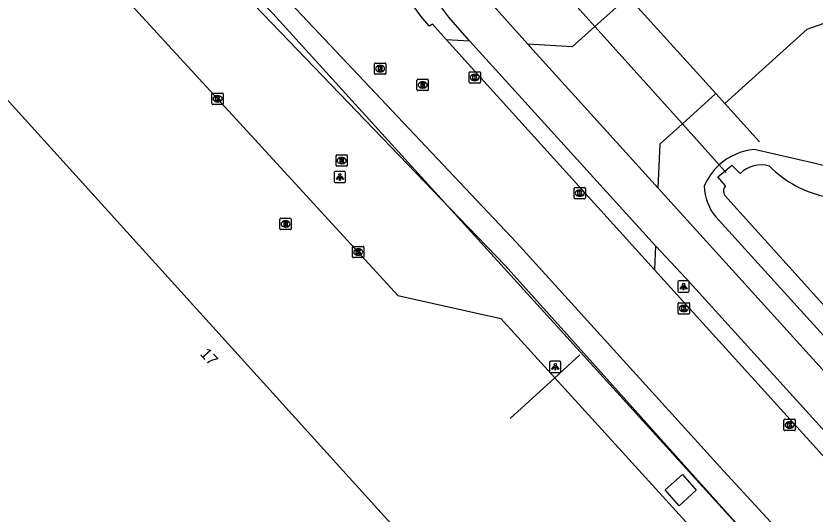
# Model space of a CAD drawing. Extents: x 156141 to 158132, y 385651 to 388399.
# Drawn here: x 156616.3 to 156687.2, y 387557.5 to 387601.7 of the extents above; entities that cross this region are included whole.
import ezdxf

# ---------------------------------------------------------------- set-up
doc = ezdxf.new("R2010")
doc.units = 0
for name, color, linetype in [('IMGEO_Berm_groen', 7, 'Continuous'), ('IMGEO_Duiker', 7, 'Continuous'), ('IMGEO_Fietspad_gesloten', 7, 'Continuous'), ('IMGEO_Groenvoorziening', 7, 'Continuous'), ('IMGEO_Hek', 7, 'Continuous'), ('IMGEO_Kolk', 7, 'Continuous'), ('IMGEO_Lichtpunt', 7, 'Continuous'), ('IMGEO_Pand', 7, 'Continuous'), ('IMGEO_Pand_nummerreeks', 7, 'Continuous'), ('IMGEO_Rijbaan_lokaal_gesloten', 7, 'Continuous'), ('IMGEO_Rijbaan_lokaal_open', 7, 'Continuous'), ('IMGEO_Rioolput', 7, 'Continuous'), ('IMGEO_Waterloop', 7, 'Continuous')]:
    doc.layers.add(name, color=color, linetype=linetype)

msp = doc.modelspace()

# ---------------------------------------------------------------- linework, layer by layer
at = {"layer": 'IMGEO_Berm_groen'}
msp.add_lwpolyline([(156619.894, 387618.693), (156621.328, 387618.297), (156622.076, 387617.962), (156623.109, 387617.268), (156623.862, 387616.763), (156654.792, 387584.595), (156659.669, 387579.524), (156664.874, 387573.724), (156670.466, 387567.492), (156676.557, 387560.705), (156683.035, 387553.487)], dxfattribs=at)
at = {"layer": 'IMGEO_Duiker'}
msp.add_lwpolyline([(156665.589, 387602.994), (156665.75, 387602.815), (156667.62, 387600.734), (156675.388, 387592.091), (156678.654, 387588.457), (156679.148, 387587.907), (156679.267, 387587.775)], dxfattribs=at)
at = {"layer": 'IMGEO_Fietspad_gesloten'}
for points in [[(156636.612, 387631.386), (156653.428, 387608.928), (156657.588, 387603.771), (156661.694, 387599.163)], [(156656.514, 387599.474), (156654.677, 387601.565), (156653.249, 387603.495), (156633.874, 387629.22)], [(156781.004, 387467.422), (156751.5, 387500), (156673.243, 387586.408)], [(156710.195, 387540.331), (156675.728, 387578.392), (156673.017, 387581.269)]]:
    msp.add_lwpolyline(points, dxfattribs=at)
at = {"layer": 'IMGEO_Groenvoorziening'}
for points in [[(156678.365, 387594.783), (156679.166, 387593.896), (156686.466, 387600.496), (156688.888, 387601.354), (156691.163, 387600.15), (156724.535, 387562.997), (156709.488, 387563.912), (156707.811, 387562.233), (156752.805, 387512.437), (156782.941, 387479.122), (156787.929, 387473.603)], [(156687.155, 387588.587), (156681.743, 387589.828)], [(156678.358, 387583.842), (156778.225, 387473.7)], [(156675.387, 387560.984), (156676.621, 387559.59), (156675.111, 387558.213), (156673.862, 387559.615), (156675.387, 387560.984)]]:
    msp.add_lwpolyline(points, dxfattribs=at)
for centre, radius, start, end in [((156682.266, 387584.485), 5.368, 95.58688, 132.27957), ((156682.592, 387584.256), 5.758, 133.14814, 156.16499), ((156675.018, 387537.83), 52.188, 67.60215, 76.55146), ((156681.767, 387586.692), 4.443, 181.40417, 219.89565)]:
    msp.add_arc(centre, radius, start, end, dxfattribs=at)
at = {"layer": 'IMGEO_Hek'}
for points in [[(156621.815, 387617.999), (156623.877, 387616.835), (156639.077, 387601.905), (156683.035, 387553.487)], [(156670.587, 387603.403), (156678.365, 387594.783), (156679.166, 387593.896), (156682.233, 387590.498)], [(156679.166, 387593.896), (156686.466, 387600.496), (156688.888, 387601.354), (156691.163, 387600.15), (156724.535, 387562.997), (156709.488, 387563.912), (156707.811, 387562.233)], [(156660.126, 387565.971), (156664.072, 387569.578), (156666.283, 387571.6)]]:
    msp.add_lwpolyline(points, dxfattribs=at)
at = {"layer": 'IMGEO_Kolk'}
for p, q in [((156656.472, 387595.791), (156656.472, 387596.643)), ((156656.547, 387596.717), (156657.399, 387596.717)), ((156656.96, 387596.497), (156656.985, 387596.497)), ((156657.473, 387596.643), (156657.473, 387595.791)), ((156657.399, 387595.717), (156656.547, 387595.717)), ((156656.983, 387595.937), (156656.958, 387595.937)), ((156633.744, 387594.83), (156634.596, 387594.83)), ((156633.669, 387593.904), (156633.669, 387594.756)), ((156634.157, 387594.61), (156634.182, 387594.61)), ((156634.67, 387594.756), (156634.67, 387593.904)), ((156634.596, 387593.83), (156633.744, 387593.83)), ((156634.18, 387594.05), (156634.155, 387594.05)), ((156665.787, 387585.525), (156665.787, 387586.377)), ((156665.862, 387586.451), (156666.714, 387586.451)), ((156666.788, 387586.377), (156666.788, 387585.525)), ((156666.298, 387585.671), (156666.273, 387585.671)), ((156666.275, 387586.231), (156666.3, 387586.231)), ((156666.714, 387585.451), (156665.862, 387585.451)), ((156646.143, 387580.303), (156646.143, 387581.155)), ((156646.218, 387581.229), (156647.07, 387581.229)), ((156646.631, 387581.009), (156646.656, 387581.009)), ((156647.144, 387581.155), (156647.144, 387580.303)), ((156647.07, 387580.229), (156646.218, 387580.229)), ((156646.654, 387580.449), (156646.629, 387580.449)), ((156675.024, 387575.302), (156675.024, 387576.154)), ((156675.099, 387576.228), (156675.951, 387576.228)), ((156675.512, 387576.008), (156675.537, 387576.008)), ((156676.025, 387576.154), (156676.025, 387575.302)), ((156675.951, 387575.228), (156675.099, 387575.228)), ((156675.535, 387575.448), (156675.51, 387575.448)), ((156684.401, 387564.958), (156684.401, 387565.81)), ((156684.476, 387565.884), (156685.328, 387565.884)), ((156685.402, 387565.81), (156685.402, 387564.958)), ((156684.912, 387565.104), (156684.887, 387565.104)), ((156684.889, 387565.664), (156684.914, 387565.664)), ((156685.328, 387564.884), (156684.476, 387564.884))]:
    msp.add_line(p, q, dxfattribs=at)
for points in [[(156656.472, 387595.791), (156656.472, 387596.643)], [(156656.547, 387596.717), (156657.399, 387596.717)], [(156656.793, 387596.417), (156656.916, 387596.417), (156656.916, 387596.266), (156657.046, 387596.417), (156657.21, 387596.417), (156657.064, 387596.266), (156657.217, 387596.017), (156657.065, 387596.017), (156656.98, 387596.181), (156656.916, 387596.114), (156656.916, 387596.017), (156656.793, 387596.017), (156656.793, 387596.417)], [(156657.473, 387596.643), (156657.473, 387595.791)], [(156657.399, 387595.717), (156656.547, 387595.717)], [(156633.744, 387594.83), (156634.596, 387594.83)], [(156633.669, 387593.904), (156633.669, 387594.756)], [(156633.99, 387594.53), (156634.113, 387594.53), (156634.113, 387594.379), (156634.243, 387594.53), (156634.407, 387594.53), (156634.261, 387594.379), (156634.414, 387594.13), (156634.262, 387594.13), (156634.177, 387594.294), (156634.113, 387594.227), (156634.113, 387594.13), (156633.99, 387594.13), (156633.99, 387594.53)], [(156634.67, 387594.756), (156634.67, 387593.904)], [(156634.596, 387593.83), (156633.744, 387593.83)], [(156665.787, 387585.525), (156665.787, 387586.377)], [(156665.862, 387586.451), (156666.714, 387586.451)], [(156666.788, 387586.377), (156666.788, 387585.525)], [(156666.108, 387586.151), (156666.231, 387586.151), (156666.231, 387586), (156666.361, 387586.151), (156666.525, 387586.151), (156666.379, 387586), (156666.532, 387585.751), (156666.38, 387585.751), (156666.295, 387585.915), (156666.231, 387585.848), (156666.231, 387585.751), (156666.108, 387585.751), (156666.108, 387586.151)], [(156666.714, 387585.451), (156665.862, 387585.451)], [(156646.143, 387580.303), (156646.143, 387581.155)], [(156646.218, 387581.229), (156647.07, 387581.229)], [(156646.464, 387580.929), (156646.587, 387580.929), (156646.587, 387580.778), (156646.717, 387580.929), (156646.881, 387580.929), (156646.735, 387580.778), (156646.888, 387580.529), (156646.736, 387580.529), (156646.651, 387580.693), (156646.587, 387580.626), (156646.587, 387580.529), (156646.464, 387580.529), (156646.464, 387580.929)], [(156647.144, 387581.155), (156647.144, 387580.303)], [(156647.07, 387580.229), (156646.218, 387580.229)], [(156675.024, 387575.302), (156675.024, 387576.154)], [(156675.099, 387576.228), (156675.951, 387576.228)], [(156675.345, 387575.928), (156675.468, 387575.928), (156675.468, 387575.777), (156675.598, 387575.928), (156675.762, 387575.928), (156675.616, 387575.777), (156675.769, 387575.528), (156675.617, 387575.528), (156675.532, 387575.692), (156675.468, 387575.625), (156675.468, 387575.528), (156675.345, 387575.528), (156675.345, 387575.928)], [(156676.025, 387576.154), (156676.025, 387575.302)], [(156675.951, 387575.228), (156675.099, 387575.228)], [(156684.401, 387564.958), (156684.401, 387565.81)], [(156684.476, 387565.884), (156685.328, 387565.884)], [(156685.402, 387565.81), (156685.402, 387564.958)], [(156684.722, 387565.584), (156684.845, 387565.584), (156684.845, 387565.433), (156684.975, 387565.584), (156685.139, 387565.584), (156684.993, 387565.433), (156685.146, 387565.184), (156684.994, 387565.184), (156684.909, 387565.348), (156684.845, 387565.281), (156684.845, 387565.184), (156684.722, 387565.184), (156684.722, 387565.584)], [(156685.328, 387564.884), (156684.476, 387564.884)]]:
    msp.add_lwpolyline(points, dxfattribs=at)
for centre, start, end in [((156656.549, 387596.641), 91.55205, 178.44795), ((156656.549, 387596.641), 91.55205, 178.44795), ((156657.397, 387596.641), 1.55205, 88.44795), ((156657.397, 387596.641), 1.55205, 88.44795), ((156656.549, 387595.793), 181.55205, 268.44795), ((156656.549, 387595.793), 181.55205, 268.44795), ((156657.397, 387595.793), 271.55205, 358.44795), ((156657.397, 387595.793), 271.55205, 358.44795), ((156633.746, 387594.754), 91.55205, 178.44795), ((156633.746, 387594.754), 91.55205, 178.44795), ((156634.594, 387594.754), 1.55205, 88.44795), ((156634.594, 387594.754), 1.55205, 88.44795), ((156633.746, 387593.906), 181.55205, 268.44795), ((156633.746, 387593.906), 181.55205, 268.44795), ((156634.594, 387593.906), 271.55205, 358.44795), ((156634.594, 387593.906), 271.55205, 358.44795), ((156665.864, 387586.375), 91.55205, 178.44795), ((156665.864, 387586.375), 91.55205, 178.44795), ((156666.712, 387586.375), 1.55205, 88.44795), ((156666.712, 387586.375), 1.55205, 88.44795), ((156665.864, 387585.527), 181.55205, 268.44795), ((156665.864, 387585.527), 181.55205, 268.44795), ((156666.712, 387585.527), 271.55205, 358.44795), ((156666.712, 387585.527), 271.55205, 358.44795), ((156646.22, 387581.153), 91.55205, 178.44795), ((156646.22, 387581.153), 91.55205, 178.44795), ((156647.068, 387581.153), 1.55205, 88.44795), ((156647.068, 387581.153), 1.55205, 88.44795), ((156646.22, 387580.305), 181.55205, 268.44795), ((156646.22, 387580.305), 181.55205, 268.44795), ((156647.068, 387580.305), 271.55205, 358.44795), ((156647.068, 387580.305), 271.55205, 358.44795), ((156675.101, 387576.152), 91.55205, 178.44795), ((156675.101, 387576.152), 91.55205, 178.44795), ((156675.949, 387576.152), 1.55205, 88.44795), ((156675.949, 387576.152), 1.55205, 88.44795), ((156675.101, 387575.304), 181.55205, 268.44795), ((156675.101, 387575.304), 181.55205, 268.44795), ((156675.949, 387575.304), 271.55205, 358.44795), ((156675.949, 387575.304), 271.55205, 358.44795), ((156684.478, 387565.808), 91.55205, 178.44795), ((156684.478, 387565.808), 91.55205, 178.44795), ((156685.326, 387565.808), 1.55205, 88.44795), ((156685.326, 387565.808), 1.55205, 88.44795), ((156684.478, 387564.96), 181.55205, 268.44795), ((156684.478, 387564.96), 181.55205, 268.44795), ((156685.326, 387564.96), 271.55205, 358.44795), ((156685.326, 387564.96), 271.55205, 358.44795)]:
    msp.add_arc(centre, 0.0765, start, end, dxfattribs=at)
for centre, major_axis, ratio, start_param, end_param in [((156656.959, 387596.217), (-0.387, 0.002), 0.722429, 4.712389, 7.853982), ((156656.984, 387596.217), (-0.39, 0.002), 0.717154, 1.570796, 4.712389), ((156634.156, 387594.33), (-0.387, 0.002), 0.722429, 4.712389, 7.853982), ((156634.181, 387594.33), (-0.39, 0.002), 0.717154, 1.570796, 4.712389), ((156666.274, 387585.951), (-0.387, 0.002), 0.722429, 4.712389, 7.853982), ((156666.299, 387585.951), (-0.39, 0.002), 0.717154, 1.570796, 4.712389), ((156646.63, 387580.729), (-0.387, 0.002), 0.722429, 4.712389, 7.853982), ((156646.655, 387580.729), (-0.39, 0.002), 0.717154, 1.570796, 4.712389), ((156675.511, 387575.728), (-0.387, 0.002), 0.722429, 4.712389, 7.853982), ((156675.536, 387575.728), (-0.39, 0.002), 0.717154, 1.570796, 4.712389), ((156684.888, 387565.384), (-0.387, 0.002), 0.722429, 4.712389, 7.853982), ((156684.913, 387565.384), (-0.39, 0.002), 0.717154, 1.570796, 4.712389)]:
    msp.add_ellipse(centre, major_axis=major_axis, ratio=ratio, start_param=start_param, end_param=end_param, dxfattribs=at)
at = {"layer": 'IMGEO_Lichtpunt'}
for p, q in [((156644.511, 387587.787), (156644.511, 387586.98)), ((156644.511, 387587.787), (156644.511, 387586.98)), ((156645.413, 387587.882), (156644.605, 387587.882)), ((156645.413, 387587.882), (156644.605, 387587.882)), ((156645.507, 387586.98), (156645.507, 387587.787)), ((156645.507, 387586.98), (156645.507, 387587.787)), ((156644.605, 387586.886), (156645.413, 387586.886)), ((156644.605, 387586.886), (156645.413, 387586.886)), ((156674.996, 387578.071), (156674.996, 387577.264)), ((156674.996, 387578.071), (156674.996, 387577.264)), ((156675.898, 387578.166), (156675.09, 387578.166)), ((156675.898, 387578.166), (156675.09, 387578.166)), ((156675.992, 387577.264), (156675.992, 387578.071)), ((156675.992, 387577.264), (156675.992, 387578.071)), ((156675.09, 387577.17), (156675.898, 387577.17)), ((156675.09, 387577.17), (156675.898, 387577.17)), ((156663.619, 387570.94), (156663.619, 387570.133)), ((156663.619, 387570.94), (156663.619, 387570.133)), ((156664.521, 387571.035), (156663.713, 387571.035)), ((156664.521, 387571.035), (156663.713, 387571.035)), ((156664.615, 387570.133), (156664.615, 387570.94)), ((156664.615, 387570.133), (156664.615, 387570.94)), ((156663.713, 387570.039), (156664.521, 387570.039)), ((156663.713, 387570.039), (156664.521, 387570.039))]:
    msp.add_line(p, q, dxfattribs=at)
for points in [[(156644.885, 387587.451), (156644.924, 387587.423), (156644.736, 387587.161), (156644.698, 387587.188), (156644.885, 387587.451)], [(156644.987, 387587.403), (156645.034, 387587.403), (156645.034, 387587.081), (156644.987, 387587.081), (156644.987, 387587.403)], [(156645.097, 387587.423), (156645.135, 387587.45), (156645.322, 387587.188), (156645.283, 387587.16), (156645.097, 387587.423)], [(156675.37, 387577.735), (156675.409, 387577.707), (156675.221, 387577.445), (156675.183, 387577.472), (156675.37, 387577.735)], [(156675.472, 387577.687), (156675.519, 387577.687), (156675.519, 387577.365), (156675.472, 387577.365), (156675.472, 387577.687)], [(156675.582, 387577.707), (156675.62, 387577.734), (156675.807, 387577.472), (156675.768, 387577.444), (156675.582, 387577.707)], [(156663.993, 387570.604), (156664.032, 387570.576), (156663.844, 387570.314), (156663.806, 387570.341), (156663.993, 387570.604)], [(156664.095, 387570.556), (156664.142, 387570.556), (156664.142, 387570.234), (156664.095, 387570.234), (156664.095, 387570.556)], [(156664.205, 387570.576), (156664.243, 387570.603), (156664.43, 387570.341), (156664.391, 387570.313), (156664.205, 387570.576)]]:
    msp.add_lwpolyline(points, dxfattribs=at)
for centre in [(156645.01, 387587.585), (156675.495, 387577.869), (156664.118, 387570.738)]:
    msp.add_circle(centre, 0.0994, dxfattribs=at)
for centre, start, end in [((156644.605, 387587.787), 90, 180), ((156644.605, 387587.787), 90, 180), ((156645.413, 387587.787), 0, 90), ((156645.413, 387587.787), 0, 90), ((156644.605, 387586.98), 180, 270), ((156644.605, 387586.98), 180, 270), ((156645.413, 387586.98), 270, 0), ((156645.413, 387586.98), 270, 360), ((156675.09, 387578.071), 90, 180), ((156675.09, 387578.071), 90, 180), ((156675.898, 387578.071), 0, 90), ((156675.898, 387578.071), 0, 90), ((156675.09, 387577.264), 180, 270), ((156675.09, 387577.264), 180, 270), ((156675.898, 387577.264), 270, 0), ((156675.898, 387577.264), 270, 360), ((156663.713, 387570.94), 90, 180), ((156663.713, 387570.94), 90, 180), ((156664.521, 387570.94), 0, 90), ((156664.521, 387570.94), 0, 90), ((156663.713, 387570.133), 180, 270), ((156663.713, 387570.133), 180, 270), ((156664.521, 387570.133), 270, 0), ((156664.521, 387570.133), 270, 360)]:
    msp.add_arc(centre, 0.0946, start, end, dxfattribs=at)
at = {"layer": 'IMGEO_Pand'}
msp.add_lwpolyline([(156649.493, 387556.673), (156611.15, 387599.011), (156601.503, 387590.29)], dxfattribs=at)
at = {"layer": 'IMGEO_Rijbaan_lokaal_gesloten'}
for points in [[(156654.437, 387599.58), (156653.22, 387600.956), (156652.968, 387600.758), (156652.324, 387601.511), (156643.266, 387613.813), (156635.328, 387624.409), (156631.221, 387629.55)], [(156622.677, 387622.734), (156627.604, 387616.653), (156660.668, 387581.568), (156679.046, 387561.32), (156683.223, 387556.751)], [(156620.65, 387609.049), (156621.494, 387608.144), (156634.17, 387594.33), (156646.644, 387580.729), (156650.158, 387576.878), (156659.292, 387574.843), (156664.072, 387569.578), (156678.969, 387553.169)], [(156672.91, 387579.145), (156654.437, 387599.58)], [(156709.034, 387539.277), (156672.91, 387579.145)]]:
    msp.add_lwpolyline(points, dxfattribs=at)
at = {"layer": 'IMGEO_Rijbaan_lokaal_open'}
for points in [[(156670.587, 387603.403), (156667.62, 387600.734), (156665.621, 387598.937), (156661.694, 387599.163)], [(156678.365, 387594.783), (156670.587, 387603.403)], [(156654.437, 387599.58), (156656.514, 387599.474)], [(156673.017, 387581.269), (156656.514, 387599.474)], [(156661.694, 387599.163), (156661.859, 387598.978), (156673.243, 387586.408)], [(156673.243, 387586.408), (156673.43, 387590.319), (156675.388, 387592.091), (156678.365, 387594.783)], [(156673.017, 387581.269), (156672.91, 387579.145)]]:
    msp.add_lwpolyline(points, dxfattribs=at)
at = {"layer": 'IMGEO_Rioolput'}
for p, q in [((156648.082, 387596.574), (156648.082, 387597.426)), ((156648.157, 387597.5), (156649.009, 387597.5)), ((156648.57, 387597.28), (156648.595, 387597.28)), ((156649.083, 387597.426), (156649.083, 387596.574)), ((156649.009, 387596.5), (156648.157, 387596.5)), ((156648.593, 387596.72), (156648.568, 387596.72)), ((156651.852, 387595.127), (156651.852, 387595.979)), ((156651.927, 387596.053), (156652.779, 387596.053)), ((156652.34, 387595.833), (156652.365, 387595.833)), ((156652.853, 387595.979), (156652.853, 387595.127)), ((156652.779, 387595.053), (156651.927, 387595.053)), ((156652.363, 387595.273), (156652.338, 387595.273)), ((156644.672, 387588.414), (156644.672, 387589.266)), ((156644.747, 387589.34), (156645.599, 387589.34)), ((156645.16, 387589.12), (156645.185, 387589.12)), ((156645.673, 387589.266), (156645.673, 387588.414)), ((156645.183, 387588.56), (156645.158, 387588.56)), ((156645.599, 387588.34), (156644.747, 387588.34)), ((156639.697, 387582.794), (156639.697, 387583.646)), ((156639.772, 387583.72), (156640.624, 387583.72)), ((156640.185, 387583.5), (156640.21, 387583.5)), ((156640.698, 387583.646), (156640.698, 387582.794)), ((156640.624, 387582.72), (156639.772, 387582.72)), ((156640.208, 387582.94), (156640.183, 387582.94))]:
    msp.add_line(p, q, dxfattribs=at)
for points in [[(156648.082, 387596.574), (156648.082, 387597.426)], [(156648.157, 387597.5), (156649.009, 387597.5)], [(156648.671, 387597.198), (156648.419, 387597.2), (156648.419, 387596.8)], [(156648.419, 387596.8), (156648.543, 387596.8), (156648.543, 387596.962), (156648.554, 387596.962)], [(156648.597, 387597.119), (156648.543, 387597.119), (156648.543, 387597.038)], [(156648.543, 387597.038), (156648.595, 387597.038)], [(156648.601, 387596.933), (156648.672, 387596.8), (156648.812, 387596.8), (156648.747, 387596.926)], [(156649.083, 387597.426), (156649.083, 387596.574)], [(156649.009, 387596.5), (156648.157, 387596.5)], [(156651.852, 387595.127), (156651.852, 387595.979)], [(156651.927, 387596.053), (156652.779, 387596.053)], [(156652.441, 387595.751), (156652.189, 387595.753), (156652.189, 387595.353)], [(156652.189, 387595.353), (156652.313, 387595.353), (156652.313, 387595.515), (156652.324, 387595.515)], [(156652.367, 387595.672), (156652.313, 387595.672), (156652.313, 387595.591)], [(156652.313, 387595.591), (156652.365, 387595.591)], [(156652.371, 387595.486), (156652.442, 387595.353), (156652.582, 387595.353), (156652.517, 387595.479)], [(156652.853, 387595.979), (156652.853, 387595.127)], [(156652.779, 387595.053), (156651.927, 387595.053)], [(156644.672, 387588.414), (156644.672, 387589.266)], [(156644.747, 387589.34), (156645.599, 387589.34)], [(156645.673, 387589.266), (156645.673, 387588.414)], [(156645.261, 387589.038), (156645.009, 387589.04), (156645.009, 387588.64)], [(156645.009, 387588.64), (156645.133, 387588.64), (156645.133, 387588.802), (156645.144, 387588.802)], [(156645.187, 387588.959), (156645.133, 387588.959), (156645.133, 387588.878)], [(156645.133, 387588.878), (156645.185, 387588.878)], [(156645.191, 387588.773), (156645.262, 387588.64), (156645.402, 387588.64), (156645.337, 387588.766)], [(156645.599, 387588.34), (156644.747, 387588.34)], [(156639.697, 387582.794), (156639.697, 387583.646)], [(156639.772, 387583.72), (156640.624, 387583.72)], [(156640.698, 387583.646), (156640.698, 387582.794)], [(156640.624, 387582.72), (156639.772, 387582.72)], [(156640.286, 387583.418), (156640.034, 387583.42), (156640.034, 387583.02)], [(156640.034, 387583.02), (156640.158, 387583.02), (156640.158, 387583.182), (156640.169, 387583.182)], [(156640.212, 387583.339), (156640.158, 387583.339), (156640.158, 387583.258)], [(156640.158, 387583.258), (156640.21, 387583.258)], [(156640.216, 387583.153), (156640.287, 387583.02), (156640.427, 387583.02), (156640.362, 387583.146)]]:
    msp.add_lwpolyline(points, dxfattribs=at)
for centre, radius, start, end in [((156648.159, 387597.424), 0.0765, 91.55205, 178.44795), ((156648.159, 387597.424), 0.0765, 91.55205, 178.44795), ((156648.553, 387596.909), 0.0533, 26.02933, 88.69889), ((156648.579, 387597.227), 0.19, 274.7715, 282.96867), ((156648.603, 387597.023), 0.0964, 77.00612, 93.18647), ((156648.617, 387597.08), 0.0378, 276.66336, 79.67722), ((156648.67, 387597.088), 0.109, 350.36119, 89.41601), ((156648.668, 387597.088), 0.112, 277.58423, 350.98172), ((156648.652, 387596.873), 0.108, 29.51342, 73.79051), ((156649.007, 387597.424), 0.0765, 1.55205, 88.44795), ((156649.007, 387597.424), 0.0765, 1.55205, 88.44795), ((156648.159, 387596.576), 0.0765, 181.55205, 268.44795), ((156648.159, 387596.576), 0.0765, 181.55205, 268.44795), ((156649.007, 387596.576), 0.0765, 271.55205, 358.44795), ((156649.007, 387596.576), 0.0765, 271.55205, 358.44795), ((156651.929, 387595.977), 0.0765, 91.55205, 178.44795), ((156651.929, 387595.977), 0.0765, 91.55205, 178.44795), ((156652.323, 387595.462), 0.0533, 26.02933, 88.69889), ((156652.349, 387595.78), 0.19, 274.7715, 282.96867), ((156652.373, 387595.576), 0.0964, 77.00612, 93.18647), ((156652.387, 387595.633), 0.0378, 276.66336, 79.67722), ((156652.44, 387595.641), 0.109, 350.36119, 89.41601), ((156652.438, 387595.641), 0.112, 277.58423, 350.98172), ((156652.422, 387595.426), 0.108, 29.51342, 73.79051), ((156652.777, 387595.977), 0.0765, 1.55205, 88.44795), ((156652.777, 387595.977), 0.0765, 1.55205, 88.44795), ((156651.929, 387595.129), 0.0765, 181.55205, 268.44795), ((156651.929, 387595.129), 0.0765, 181.55205, 268.44795), ((156652.777, 387595.129), 0.0765, 271.55205, 358.44795), ((156652.777, 387595.129), 0.0765, 271.55205, 358.44795), ((156644.749, 387589.264), 0.0765, 91.55205, 178.44795), ((156644.749, 387589.264), 0.0765, 91.55205, 178.44795), ((156645.597, 387589.264), 0.0765, 1.55205, 88.44795), ((156645.597, 387589.264), 0.0765, 1.55205, 88.44795), ((156644.749, 387588.416), 0.0765, 181.55205, 268.44795), ((156644.749, 387588.416), 0.0765, 181.55205, 268.44795), ((156645.143, 387588.749), 0.0533, 26.02933, 88.69889), ((156645.169, 387589.067), 0.19, 274.7715, 282.96867), ((156645.193, 387588.863), 0.0964, 77.00612, 93.18647), ((156645.207, 387588.92), 0.0378, 276.66336, 79.67722), ((156645.26, 387588.928), 0.109, 350.36119, 89.41601), ((156645.258, 387588.928), 0.112, 277.58423, 350.98172), ((156645.242, 387588.713), 0.108, 29.51342, 73.79051), ((156645.597, 387588.416), 0.0765, 271.55205, 358.44795), ((156645.597, 387588.416), 0.0765, 271.55205, 358.44795), ((156639.774, 387583.644), 0.0765, 91.55205, 178.44795), ((156639.774, 387583.644), 0.0765, 91.55205, 178.44795), ((156640.622, 387583.644), 0.0765, 1.55205, 88.44795), ((156640.622, 387583.644), 0.0765, 1.55205, 88.44795), ((156639.774, 387582.796), 0.0765, 181.55205, 268.44795), ((156639.774, 387582.796), 0.0765, 181.55205, 268.44795), ((156640.168, 387583.129), 0.0533, 26.02933, 88.69889), ((156640.194, 387583.447), 0.19, 274.7715, 282.96867), ((156640.218, 387583.243), 0.0964, 77.00612, 93.18647), ((156640.232, 387583.3), 0.0378, 276.66336, 79.67722), ((156640.285, 387583.308), 0.109, 350.36119, 89.41601), ((156640.283, 387583.308), 0.112, 277.58423, 350.98172), ((156640.267, 387583.093), 0.108, 29.51342, 73.79051), ((156640.622, 387582.796), 0.0765, 271.55205, 358.44795), ((156640.622, 387582.796), 0.0765, 271.55205, 358.44795)]:
    msp.add_arc(centre, radius, start, end, dxfattribs=at)
for centre, major_axis, ratio, start_param, end_param in [((156648.569, 387597), (-0.387, 0.002), 0.722429, 4.712389, 7.853982), ((156648.594, 387597), (-0.39, 0.002), 0.717154, 1.570796, 4.712389), ((156652.339, 387595.553), (-0.387, 0.002), 0.722429, 4.712389, 7.853982), ((156652.364, 387595.553), (-0.39, 0.002), 0.717154, 1.570796, 4.712389), ((156645.159, 387588.84), (-0.387, 0.002), 0.722429, 4.712389, 7.853982), ((156645.184, 387588.84), (-0.39, 0.002), 0.717154, 1.570796, 4.712389), ((156640.184, 387583.22), (-0.387, 0.002), 0.722429, 4.712389, 7.853982), ((156640.209, 387583.22), (-0.39, 0.002), 0.717154, 1.570796, 4.712389)]:
    msp.add_ellipse(centre, major_axis=major_axis, ratio=ratio, start_param=start_param, end_param=end_param, dxfattribs=at)
at = {"layer": 'IMGEO_Waterloop'}
for points in [[(156679.226, 387586.609), (156678.532, 387587.389), (156679.148, 387587.907), (156679.789, 387588.446), (156680.502, 387587.697)], [(156779.164, 387474.772), (156679.162, 387585.757)]]:
    msp.add_lwpolyline(points, dxfattribs=at)
for centre, radius, start, end in [((156682.369, 387585.789), 2.669, 73.75226, 134.38211), ((156690.065, 387595.177), 9.74, 224.48538, 259.15247), ((156679.654, 387586.148), 0.628, 132.87798, 218.53034)]:
    msp.add_arc(centre, radius, start, end, dxfattribs=at)

# ---------------------------------------------------------------- texts
at = {"layer": 'IMGEO_Pand_nummerreeks'}
msp.add_text('17', height=1, rotation=312.16375, dxfattribs=at).set_placement((156632.553, 387571.654))

doc.saveas('drawing.dxf')
